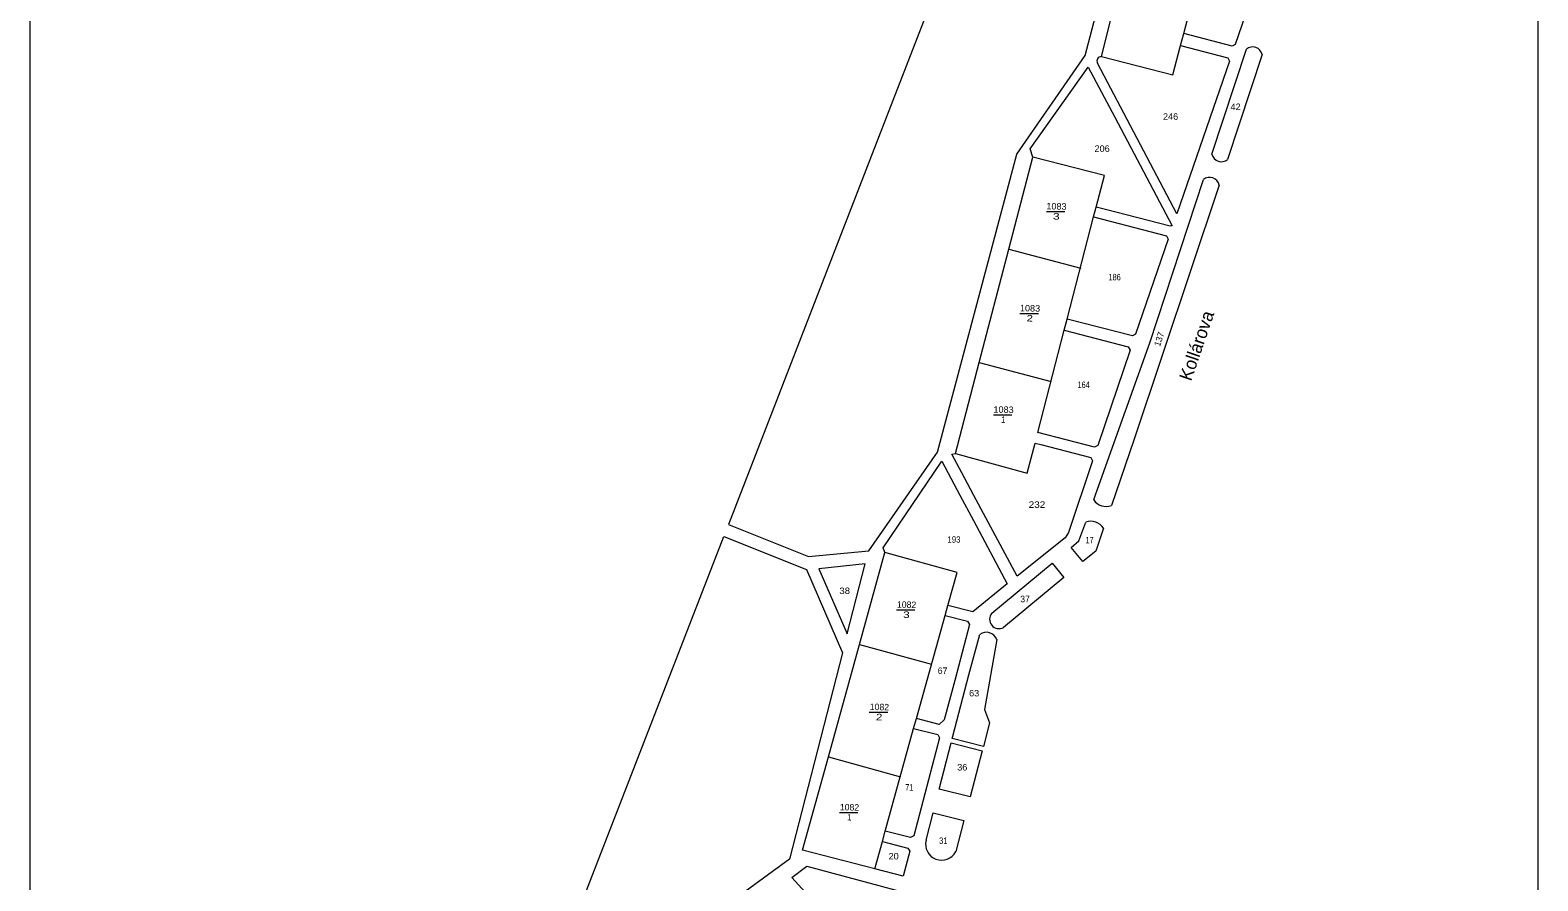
# Model space of a CAD drawing. Extents: x -843556 to -843323, y -1003151 to -1002684.
# Drawn here: x -843555.6 to -843322.7, y -1002941.7 to -1002810.3 of the extents above; entities that cross this region are included whole.
import ezdxf
from ezdxf.enums import TextEntityAlignment as Align

# ---------------------------------------------------------------- set-up
doc = ezdxf.new("R2010")
doc.units = 0
doc.header["$LTSCALE"] = 0.4
doc.layers.add('20', color=7, linetype='Continuous')
for name, color, linetype, lineweight in [('35', 7, 'Continuous', 13), ('38', 7, 'Continuous', 13), ('43', 7, 'Continuous', 13), ('44', 7, 'Continuous', 13)]:
    doc.layers.add(name, color=color, linetype=linetype, lineweight=lineweight)

msp = doc.modelspace()

# ---------------------------------------------------------------- linework, layer by layer
at = {"layer": '35'}
for p, q in [((-843398.6, -1002838.272), (-843395.746, -1002838.272)), ((-843402.685, -1002854.011), (-843399.831, -1002854.011)), ((-843406.774, -1002869.669), (-843403.92, -1002869.669)), ((-843421.753, -1002899.796), (-843418.899, -1002899.796)), ((-843425.947, -1002915.598), (-843423.093, -1002915.598)), ((-843430.57, -1002931.077), (-843427.716, -1002931.077))]:
    msp.add_line(p, q, dxfattribs=at)
at = {"layer": '38'}
for p, q in [((-843377.869, -1002812.634), (-843377.382, -1002810.775)), ((-843391.29, -1002839.12), (-843390.892, -1002837.586)), ((-843404.41, -1002844.09), (-843393.26, -1002847.01)), ((-843409, -1002861.6), (-843397.84, -1002864.52)), ((-843414.235, -1002900.673), (-843413.794, -1002899.104)), ((-843427.47, -1002905.15), (-843416.35, -1002908.21)), ((-843419.094, -1002918.138), (-843418.66, -1002916.568)), ((-843432.25, -1002922.51), (-843421.15, -1002925.58)), ((-843423.91, -1002935.552), (-843423.471, -1002933.967))]:
    msp.add_line(p, q, dxfattribs=at)
for points in [[(-843390.09, -1002814.34), (-843386.49, -1002799.97), (-843381.92, -1002782.46), (-843378.19, -1002768.18)], [(-843412.65, -1002875.63), (-843409, -1002861.6), (-843404.41, -1002844.09), (-843400.67, -1002829.87)], [(-843425.08, -1002939.78), (-843436.27, -1002936.92), (-843432.25, -1002922.51), (-843427.47, -1002905.15), (-843423.55, -1002890.94)]]:
    msp.add_lwpolyline(points, dxfattribs=at)
at = {"layer": '43'}
for p, q in [((-843373.021, -1002829.417), (-843367.684, -1002813.205)), ((-843365.264, -1002814.039), (-843370.601, -1002830.251)), ((-843395.828, -1002856.607), (-843395.38, -1002854.88)), ((-843395.883, -1002894.787), (-843405.196, -1002902.498)), ((-843411.325, -1002932.354), (-843412.58, -1002937.14))]:
    msp.add_line(p, q, dxfattribs=at)
for points in [[(-843379.548, -1002710.893), (-843422.29, -1002821.11), (-843447.677, -1002886.601), (-843435.31, -1002891.55), (-843426.04, -1002890.66), (-843415.4, -1002875.44), (-843403.14, -1002829.42), (-843392.58, -1002814.16), (-843380.16, -1002766.74), (-843369.72, -1002752.76), (-843363.099, -1002727.486), (-843372.788, -1002713.11)], [(-843373.303, -1002795.162), (-843364.697, -1002797.424), (-843364.42, -1002797.941), (-843369.418, -1002812.466), (-843369.898, -1002812.722), (-843377.382, -1002810.775)], [(-843400.67, -1002829.87), (-843401.1, -1002828.58), (-843392.12, -1002815.98), (-843388.043, -1002823.7), (-843379.182, -1002840.477), (-843379.474, -1002840.549), (-843389.453, -1002837.959), (-843390.892, -1002837.586), (-843389.633, -1002832.734)], [(-843391.29, -1002839.12), (-843380.051, -1002842.037), (-843379.774, -1002842.554), (-843384.827, -1002857.237), (-843385.306, -1002857.494), (-843395.38, -1002854.88)], [(-843395.828, -1002856.607), (-843385.948, -1002859.171), (-843385.671, -1002859.689), (-843390.656, -1002874.436), (-843391.135, -1002874.696), (-843399.93, -1002872.413)], [(-843400.326, -1002874.048), (-843399.462, -1002874.272), (-843391.73, -1002876.279), (-843391.452, -1002876.794), (-843395.18, -1002887.84), (-843395.692, -1002888.655), (-843403.119, -1002894.598), (-843409.775, -1002882.143), (-843411.24, -1002879.401), (-843413.175, -1002875.779), (-843412.65, -1002875.63), (-843401.54, -1002878.7)], [(-843423.55, -1002890.94), (-843423.79, -1002890.2), (-843414.759, -1002876.84), (-843411.953, -1002882.09), (-843409.861, -1002886.006), (-843404.626, -1002895.803), (-843409.97, -1002900.08), (-843413.794, -1002899.104), (-843412.37, -1002894.03)], [(-843426.56, -1002892.684), (-843433.751, -1002893.45), (-843429.34, -1002903.499)], [(-843414.235, -1002900.673), (-843410.772, -1002901.559), (-843410.487, -1002902.048), (-843412.758, -1002910.686), (-843414.366, -1002916.801), (-843415.172, -1002917.504), (-843418.66, -1002916.568)], [(-843419.094, -1002918.138), (-843415.371, -1002919.05), (-843415.086, -1002919.539), (-843419.07, -1002934.693), (-843419.558, -1002934.978), (-843423.471, -1002933.967)], [(-843413.301, -1002920.326), (-843408.501, -1002921.585), (-843410.366, -1002928.697), (-843415.14, -1002927.47)], [(-843423.91, -1002935.552), (-843419.981, -1002936.585), (-843419.696, -1002937.074), (-843420.704, -1002940.908), (-843425.08, -1002939.78)], [(-843437.935, -1002941.144), (-843435.58, -1002939.36), (-843424.49, -1002942.38), (-843421.44, -1002943.21), (-843424.311, -1002948.699), (-843426.76, -1002953.38), (-843430.664, -1002949.105)]]:
    msp.add_lwpolyline(points, close=True, dxfattribs=at)
for points in [[(-843377.869, -1002812.634), (-843370.586, -1002814.535), (-843370.309, -1002815.052), (-843378.418, -1002838.616), (-843390.695, -1002815.37)], [(-843390.09, -1002814.34), (-843379.05, -1002817.15), (-843377.869, -1002812.634)], [(-843391.281, -1002882.788), (-843391.003, -1002882.012), (-843388.11, -1002873.927), (-843382.619, -1002858.576), (-843374.316, -1002833.352)], [(-843371.896, -1002834.187), (-843385.026, -1002873.44), (-843388.552, -1002883.69)], [(-843389.762, -1002887.207), (-843390.97, -1002890.72), (-843392.958, -1002892.353), (-843394.772, -1002890.165), (-843393.56, -1002889.16), (-843392.522, -1002886.258)], [(-843471.66, -1002948.47), (-843448.4, -1002888.465), (-843435.631, -1002893.576), (-843430.091, -1002906.42), (-843438.29, -1002938.313), (-843448.413, -1002945.721)], [(-843407.01, -1002900.31), (-843397.702, -1002892.593), (-843395.883, -1002894.787)], [(-843408.324, -1002920.91), (-843413.128, -1002919.65), (-843413.04, -1002919.31), (-843410.57, -1002909.84), (-843408.86, -1002903.59)], [(-843406.26, -1002904.36), (-843408.15, -1002915.18), (-843407.37, -1002917.27), (-843408.324, -1002920.91)], [(-843417.18, -1002935.38), (-843416.081, -1002931.132), (-843411.325, -1002932.354)]]:
    msp.add_lwpolyline(points, dxfattribs=at)
for centre, radius, start, end in [((-843366.7291, -1002814.3618), 1.5002, 12.42745, 129.52883), ((-843390.0738, -1002815.0421), 0.7023, 91.32417, 207.83931), ((-843371.5554, -1002829.0941), 1.5003, 192.42949, 309.52684), ((-843373.3612, -1002834.5096), 1.5002, 12.4191, 129.52883), ((-843389.3384, -1002881.4905), 2.3358, 213.75026, 289.68496), ((-843391.735, -1002888.4572), 2.3358, 32.34813, 109.68496), ((-843405.9167, -1002901.2496), 1.4416, 139.32451, 299.99269), ((-843407.8555, -1002904.9727), 1.7091, 21.00728, 125.999), ((-843414.7725, -1002935.9789), 2.4809, 166.02982, 332.09561)]:
    msp.add_arc(centre, radius, start, end, dxfattribs=at)
at = {"layer": '44'}
msp.add_lwpolyline([(-843322.682, -1002683.578), (-843322.682, -1003151.23), (-843555.557, -1003151.23), (-843555.557, -1002683.578)], close=True, dxfattribs=at)

# ---------------------------------------------------------------- texts
at = {"layer": '20'}
msp.add_text('Kollárova', height=2, rotation=71.148, dxfattribs=at).set_placement((-843376.237, -1002864.583))
at = {"layer": '35'}
for s, width, p in [('1083', 1.05, (-843397.041, -1002837.9746)), ('3', 1.4, (-843397.0765, -1002839.5245)), ('1083', 1.05, (-843401.1275, -1002853.7136)), ('2', 1.35, (-843401.161, -1002855.2633)), ('1083', 1.05, (-843405.215, -1002869.3716)), ('1', 0.7, (-843405.2505, -1002870.9218)), ('3', 1.4, (-843420.2295, -1002901.0485)), ('2', 1.35, (-843424.423, -1002916.8503)), ('1', 0.7, (-843429.0475, -1002932.3298))]:
    msp.add_text(s, height=1, rotation=358.734, dxfattribs=dict(at, width=width)).set_placement(p, align=Align.CENTER)
for p in [(-843420.194, -1002899.4994), (-843424.388, -1002915.3004), (-843429.012, -1002930.7804)]:
    msp.add_text('1082', height=1, rotation=358.734, dxfattribs=at).set_placement(p, align=Align.CENTER)
at = {"layer": '43'}
for s, width, p in [('42', 1.05, (-843370.146, -1002822.602)), ('246', 1.05, (-843380.583, -1002824.118)), ('206', 1.05, (-843391.151, -1002829.07)), ('186', 0.85, (-843389, -1002848.909)), ('164', 0.85, (-843393.788, -1002865.537)), ('232', 1.15, (-843401.33, -1002884.046)), ('193', 0.9, (-843413.869, -1002889.434)), ('17', 0.7, (-843392.547, -1002889.532)), ('38', 1.1, (-843430.559, -1002897.356)), ('63', 1.05, (-843410.53, -1002913.168)), ('36', 1.05, (-843412.365, -1002924.609)), ('71', 0.7, (-843420.399, -1002927.715)), ('31', 0.8, (-843415.158, -1002935.956)), ('20', 1.05, (-843422.964, -1002938.348))]:
    msp.add_text(s, height=1, dxfattribs=dict(at, width=width)).set_placement(p)
msp.add_text('137', height=1, rotation=71.78, dxfattribs=at).set_placement((-843381.049, -1002859.204))
for s, p in [('37', (-843402.628, -1002898.624)), ('67', (-843415.37, -1002909.696))]:
    msp.add_text(s, height=1, dxfattribs=at).set_placement(p)

doc.saveas('drawing.dxf')
